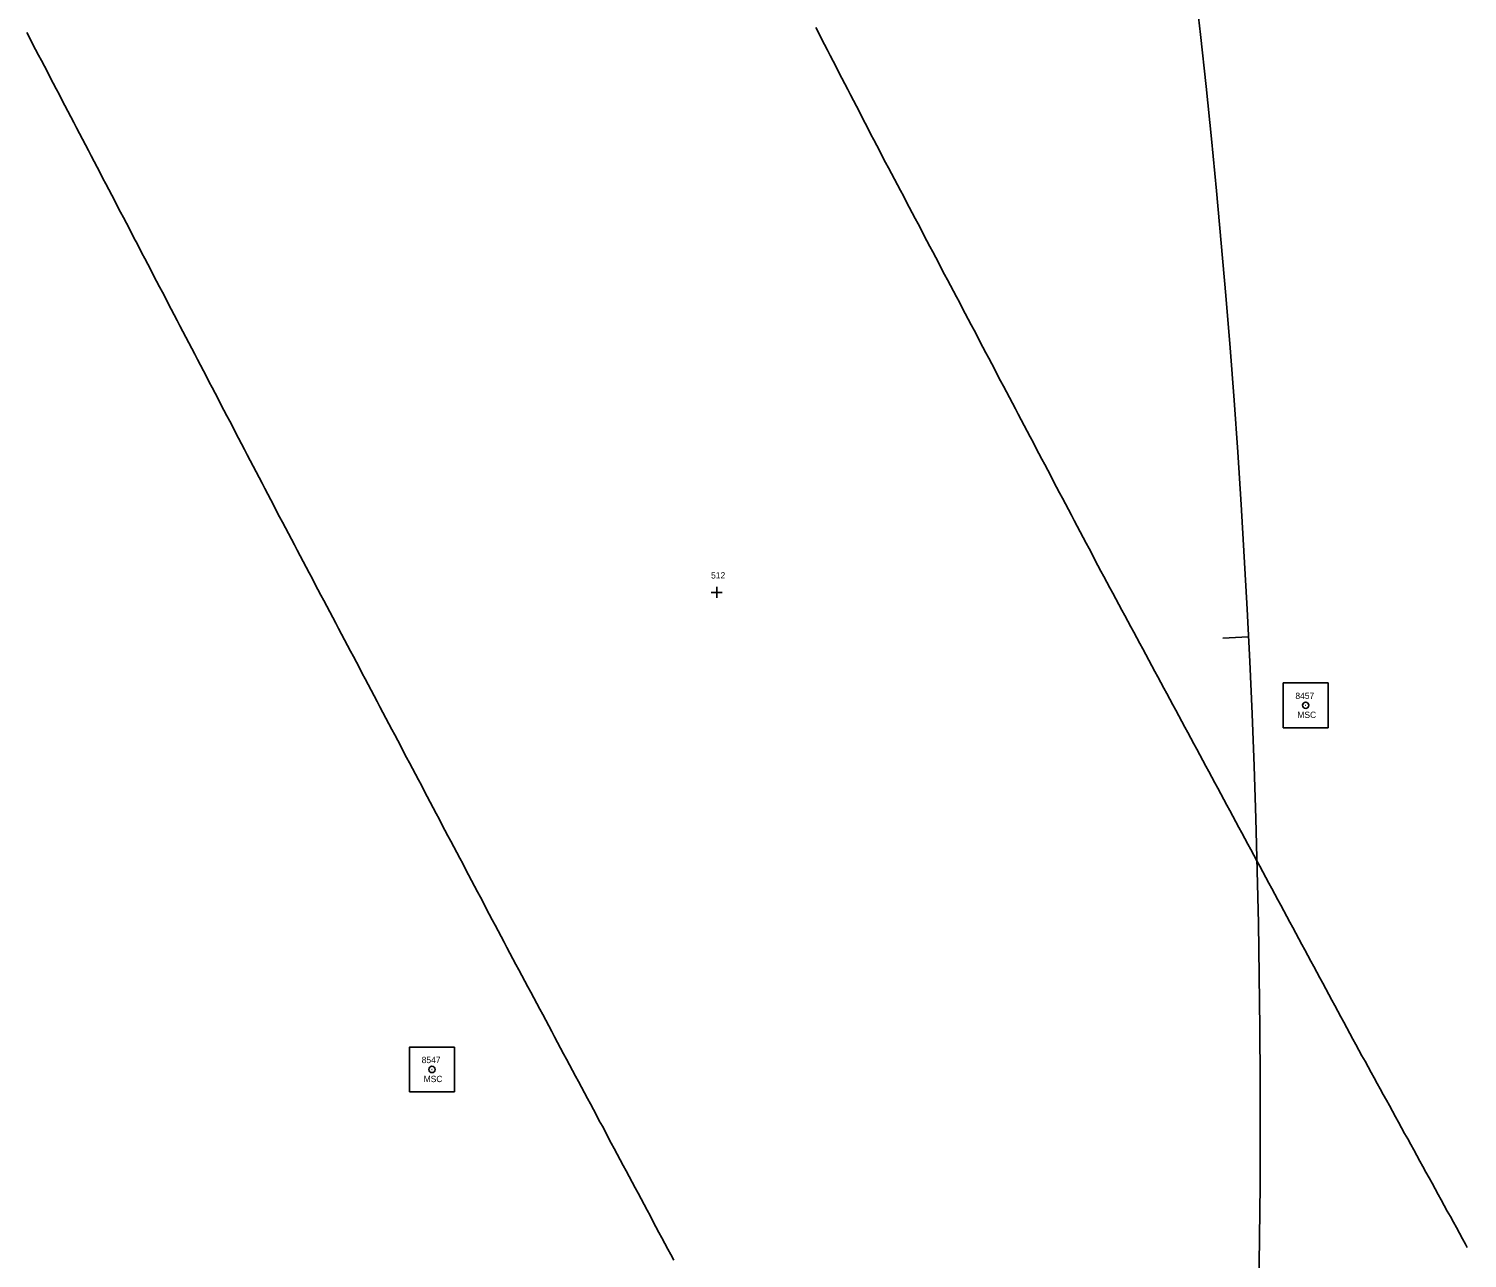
# Model space of a CAD drawing. Extents: x 205929 to 2357175, y -1785700 to 846739.
# Drawn here: x 2013567.6 to 2013794.9, y 822485.6 to 822679.9 of the extents above; entities that cross this region are included whole.
import ezdxf

# ---------------------------------------------------------------- set-up
doc = ezdxf.new("R2010")
doc.units = 0
for name, color, linetype in [('Default', 7, 'Continuous'), ('RD_HC_Cl', 7, 'Continuous'), ('RD_HC_Survey', 7, 'Continuous'), ('RD_HC_txCode', 7, 'Continuous'), ('RD_Sketch1', 7, 'Continuous'), ('RD_SMD_Locator', 7, 'Continuous')]:
    doc.layers.add(name, color=color, linetype=linetype)

msp = doc.modelspace()

# ---------------------------------------------------------------- linework, layer by layer
at = {"layer": 'Default'}
for p, q in [((2013677.23, 822590.79), (2013675.48, 822590.79)), ((2013676.35, 822591.66), (2013676.35, 822589.91))]:
    msp.add_line(p, q, dxfattribs=at)
at = {"layer": 'RD_HC_Cl'}
msp.add_line((2013760.34, 822583.77), (2013756.34, 822583.57), dxfattribs=at)
msp.add_arc((2012212.23, 822507.3), 1550, 316.11868, 35.79564, dxfattribs=at)
at = {"layer": 'RD_HC_Survey'}
for points in [[(2013772.95, 822576.48), (2013765.88, 822576.48), (2013765.88, 822569.41), (2013772.95, 822569.41)], [(2013634.89, 822518.95), (2013627.82, 822518.95), (2013627.82, 822511.88), (2013634.89, 822511.88)]]:
    msp.add_lwpolyline(points, close=True, dxfattribs=at)
for centre in [(2013769.42, 822572.95), (2013631.36, 822515.41)]:
    msp.add_circle(centre, 0.5, dxfattribs=at)
at = {"layer": 'RD_Sketch1'}
for points in [[(2013692, 822680.05), (2013692.46, 822679.17), (2013692.92, 822678.28), (2013693.38, 822677.39), (2013693.84, 822676.5), (2013694.3, 822675.61), (2013694.76, 822674.72), (2013695.22, 822673.83), (2013695.67, 822672.95), (2013696.13, 822672.06), (2013696.59, 822671.17), (2013697.05, 822670.28), (2013697.51, 822669.39), (2013697.97, 822668.5), (2013698.43, 822667.61), (2013698.89, 822666.73), (2013699.34, 822665.84), (2013699.8, 822664.95), (2013700.26, 822664.06), (2013700.72, 822663.17), (2013701.18, 822662.28), (2013701.64, 822661.4), (2013702.11, 822660.51), (2013702.57, 822659.63), (2013703.04, 822658.74), (2013703.51, 822657.86), (2013703.97, 822656.97), (2013704.44, 822656.09), (2013704.9, 822655.2), (2013705.37, 822654.32), (2013705.84, 822653.44), (2013706.3, 822652.55), (2013706.77, 822651.67), (2013707.23, 822650.78), (2013707.7, 822649.9), (2013708.16, 822649.01), (2013708.63, 822648.13), (2013709.1, 822647.24), (2013709.56, 822646.36), (2013710.03, 822645.47), (2013710.49, 822644.59), (2013710.96, 822643.71), (2013711.43, 822642.82), (2013711.89, 822641.94), (2013712.36, 822641.05), (2013712.82, 822640.17), (2013713.29, 822639.28), (2013713.75, 822638.4), (2013714.22, 822637.51), (2013714.69, 822636.63), (2013715.15, 822635.74), (2013715.62, 822634.86), (2013716.08, 822633.98), (2013716.55, 822633.09), (2013717.02, 822632.21), (2013717.48, 822631.32), (2013717.95, 822630.44), (2013718.41, 822629.55), (2013718.88, 822628.67), (2013719.35, 822627.78), (2013719.81, 822626.9), (2013720.28, 822626.01), (2013720.74, 822625.13), (2013721.21, 822624.24), (2013721.67, 822623.36), (2013722.14, 822622.48), (2013722.61, 822621.59), (2013723.07, 822620.71), (2013723.54, 822619.82), (2013724, 822618.94), (2013724.47, 822618.05), (2013724.94, 822617.17), (2013725.4, 822616.28), (2013725.87, 822615.4), (2013726.33, 822614.51), (2013726.8, 822613.63), (2013727.26, 822612.75), (2013727.73, 822611.86), (2013728.2, 822610.98), (2013728.66, 822610.09), (2013729.13, 822609.21), (2013729.59, 822608.32), (2013730.06, 822607.44), (2013730.53, 822606.55), (2013730.99, 822605.67), (2013731.46, 822604.78), (2013731.92, 822603.9), (2013732.39, 822603.02), (2013732.85, 822602.13), (2013733.32, 822601.25), (2013733.79, 822600.36), (2013734.25, 822599.48), (2013734.72, 822598.59), (2013735.18, 822597.71), (2013735.65, 822596.82), (2013736.12, 822595.94), (2013736.58, 822595.05), (2013737.05, 822594.17), (2013737.53, 822593.29), (2013738, 822592.41), (2013738.47, 822591.53), (2013738.95, 822590.65), (2013739.42, 822589.77), (2013739.9, 822588.89), (2013740.37, 822588.01), (2013740.84, 822587.13), (2013741.32, 822586.25), (2013741.79, 822585.37), (2013742.27, 822584.49), (2013742.74, 822583.61), (2013743.21, 822582.73), (2013743.69, 822581.85), (2013744.16, 822580.97), (2013744.64, 822580.08), (2013745.11, 822579.2), (2013745.59, 822578.32), (2013746.06, 822577.44), (2013746.53, 822576.56), (2013747.01, 822575.68), (2013747.48, 822574.8), (2013747.96, 822573.92), (2013748.43, 822573.04), (2013748.9, 822572.16), (2013749.38, 822571.28), (2013749.85, 822570.4), (2013750.33, 822569.52), (2013750.8, 822568.64), (2013751.27, 822567.76), (2013751.75, 822566.88), (2013752.22, 822566), (2013752.7, 822565.12), (2013753.17, 822564.24), (2013753.64, 822563.36), (2013754.12, 822562.48), (2013754.59, 822561.6), (2013755.07, 822560.72), (2013755.54, 822559.84), (2013756.01, 822558.95), (2013756.49, 822558.07), (2013756.96, 822557.19), (2013757.44, 822556.31), (2013757.91, 822555.43), (2013758.38, 822554.55), (2013758.86, 822553.67), (2013759.33, 822552.79), (2013759.81, 822551.91), (2013760.28, 822551.03), (2013760.75, 822550.15), (2013761.23, 822549.27), (2013761.7, 822548.39), (2013762.18, 822547.51), (2013762.65, 822546.63), (2013763.12, 822545.75), (2013763.6, 822544.87), (2013764.07, 822543.99), (2013764.55, 822543.11), (2013765.02, 822542.23), (2013765.5, 822541.35), (2013765.97, 822540.47), (2013766.44, 822539.59), (2013766.92, 822538.71), (2013767.39, 822537.82), (2013767.87, 822536.94), (2013768.34, 822536.06), (2013768.81, 822535.18), (2013769.29, 822534.3), (2013769.76, 822533.42), (2013770.24, 822532.54), (2013770.71, 822531.66), (2013771.18, 822530.78), (2013771.66, 822529.9), (2013772.13, 822529.02), (2013772.61, 822528.14), (2013773.08, 822527.26), (2013773.55, 822526.38), (2013774.03, 822525.5), (2013774.5, 822524.62), (2013774.98, 822523.74), (2013775.45, 822522.86), (2013775.92, 822521.98), (2013776.4, 822521.1), (2013776.87, 822520.22), (2013777.35, 822519.34), (2013777.83, 822518.46), (2013778.31, 822517.58), (2013778.79, 822516.71), (2013779.27, 822515.83), (2013779.76, 822514.95), (2013780.24, 822514.08), (2013780.72, 822513.2), (2013781.2, 822512.33), (2013781.68, 822511.45), (2013782.16, 822510.57), (2013782.64, 822509.7), (2013783.12, 822508.82), (2013783.61, 822507.94), (2013784.09, 822507.07), (2013784.57, 822506.19), (2013785.05, 822505.31), (2013785.53, 822504.44), (2013786.01, 822503.56), (2013786.49, 822502.69), (2013786.98, 822501.81), (2013787.46, 822500.93), (2013787.94, 822500.06), (2013788.42, 822499.18), (2013788.9, 822498.3), (2013789.38, 822497.43), (2013789.86, 822496.55), (2013790.34, 822495.67), (2013790.83, 822494.8), (2013791.31, 822493.92), (2013791.79, 822493.04), (2013792.27, 822492.17), (2013792.75, 822491.29), (2013793.23, 822490.42), (2013793.71, 822489.54), (2013794.2, 822488.66), (2013794.68, 822487.79), (2013794.94, 822487.3)], [(2013567.33, 822679.26), (2013567.8, 822678.37), (2013568.26, 822677.48), (2013568.72, 822676.6), (2013569.19, 822675.71), (2013569.65, 822674.82), (2013570.11, 822673.94), (2013570.58, 822673.05), (2013571.04, 822672.16), (2013571.5, 822671.28), (2013571.96, 822670.39), (2013572.43, 822669.51), (2013572.89, 822668.62), (2013573.35, 822667.73), (2013573.82, 822666.85), (2013574.28, 822665.96), (2013574.74, 822665.07), (2013575.21, 822664.19), (2013575.67, 822663.3), (2013576.13, 822662.42), (2013576.59, 822661.53), (2013577.06, 822660.64), (2013577.52, 822659.76), (2013577.98, 822658.87), (2013578.45, 822657.98), (2013578.91, 822657.1), (2013579.37, 822656.21), (2013579.84, 822655.33), (2013580.3, 822654.44), (2013580.76, 822653.55), (2013581.22, 822652.67), (2013581.69, 822651.78), (2013582.15, 822650.89), (2013582.61, 822650.01), (2013583.08, 822649.12), (2013583.54, 822648.24), (2013584, 822647.35), (2013584.47, 822646.46), (2013584.61, 822646.19), (2013585.07, 822645.31), (2013585.53, 822644.42), (2013585.99, 822643.54), (2013586.46, 822642.65), (2013586.92, 822641.76), (2013587.38, 822640.88), (2013587.84, 822639.99), (2013588.31, 822639.1), (2013588.77, 822638.22), (2013589.23, 822637.33), (2013589.69, 822636.44), (2013590.16, 822635.56), (2013590.62, 822634.67), (2013591.08, 822633.78), (2013591.54, 822632.9), (2013592.01, 822632.01), (2013592.47, 822631.12), (2013592.93, 822630.24), (2013593.4, 822629.35), (2013593.86, 822628.46), (2013594.32, 822627.58), (2013594.78, 822626.69), (2013595.25, 822625.8), (2013595.71, 822624.92), (2013596.17, 822624.03), (2013596.63, 822623.15), (2013597.1, 822622.26), (2013597.56, 822621.37), (2013598.02, 822620.49), (2013598.48, 822619.6), (2013598.95, 822618.71), (2013599.41, 822617.83), (2013599.87, 822616.94), (2013600.33, 822616.05), (2013600.8, 822615.17), (2013601.26, 822614.28), (2013601.72, 822613.39), (2013602.18, 822612.51), (2013602.65, 822611.62), (2013603.11, 822610.73), (2013603.57, 822609.85), (2013604.03, 822608.96), (2013604.5, 822608.07), (2013604.96, 822607.19), (2013605.42, 822606.3), (2013605.88, 822605.41), (2013606.35, 822604.53), (2013606.81, 822603.64), (2013607.27, 822602.76), (2013607.74, 822601.87), (2013608.21, 822600.99), (2013608.67, 822600.1), (2013609.14, 822599.22), (2013609.61, 822598.33), (2013610.07, 822597.45), (2013610.54, 822596.57), (2013611.01, 822595.68), (2013611.47, 822594.8), (2013611.94, 822593.91), (2013612.41, 822593.03), (2013612.87, 822592.14), (2013613.34, 822591.26), (2013613.81, 822590.37), (2013614.27, 822589.49), (2013614.74, 822588.61), (2013615.21, 822587.72), (2013615.67, 822586.84), (2013616.14, 822585.95), (2013616.61, 822585.07), (2013617.07, 822584.18), (2013617.54, 822583.3), (2013618.01, 822582.42), (2013618.47, 822581.53), (2013618.94, 822580.65), (2013619.41, 822579.76), (2013619.88, 822578.88), (2013620.34, 822577.99), (2013620.81, 822577.11), (2013621.28, 822576.22), (2013621.74, 822575.34), (2013622.21, 822574.46), (2013622.68, 822573.57), (2013623.14, 822572.69), (2013623.61, 822571.8), (2013624.08, 822570.92), (2013624.54, 822570.03), (2013625.01, 822569.15), (2013625.48, 822568.27), (2013625.94, 822567.38), (2013626.41, 822566.5), (2013626.88, 822565.61), (2013627.34, 822564.73), (2013627.81, 822563.84), (2013628.28, 822562.96), (2013628.74, 822562.07), (2013629.21, 822561.19), (2013629.68, 822560.31), (2013630.14, 822559.42), (2013630.61, 822558.54), (2013631.08, 822557.65), (2013631.54, 822556.77), (2013632.01, 822555.88), (2013632.48, 822555), (2013632.94, 822554.12), (2013633.41, 822553.23), (2013633.88, 822552.35), (2013634.34, 822551.46), (2013634.81, 822550.58), (2013635.28, 822549.69), (2013635.74, 822548.81), (2013636.21, 822547.93), (2013636.68, 822547.04), (2013637.14, 822546.16), (2013637.61, 822545.27), (2013638.08, 822544.39), (2013638.54, 822543.5), (2013639.01, 822542.62), (2013639.48, 822541.73), (2013639.94, 822540.85), (2013640.41, 822539.97), (2013640.88, 822539.08), (2013641.34, 822538.2), (2013641.81, 822537.31), (2013642.28, 822536.43), (2013642.74, 822535.54), (2013643.21, 822534.66), (2013643.68, 822533.78), (2013644.15, 822532.89), (2013644.62, 822532.01), (2013645.09, 822531.13), (2013645.56, 822530.25), (2013646.03, 822529.36), (2013646.5, 822528.48), (2013646.97, 822527.6), (2013647.44, 822526.72), (2013647.91, 822525.84), (2013648.39, 822524.95), (2013648.86, 822524.07), (2013649.33, 822523.19), (2013649.8, 822522.31), (2013650.27, 822521.43), (2013650.74, 822520.54), (2013651.21, 822519.66), (2013651.68, 822518.78), (2013652.15, 822517.9), (2013652.62, 822517.02), (2013653.1, 822516.13), (2013653.57, 822515.25), (2013654.04, 822514.37), (2013654.51, 822513.49), (2013654.98, 822512.61), (2013655.45, 822511.72), (2013655.92, 822510.84), (2013656.39, 822509.96), (2013656.86, 822509.08), (2013657.33, 822508.2), (2013657.8, 822507.31), (2013658.28, 822506.43), (2013658.75, 822505.55), (2013659.22, 822504.67), (2013659.69, 822503.79), (2013660.16, 822502.9), (2013660.63, 822502.02), (2013661.1, 822501.14), (2013661.57, 822500.26), (2013662.04, 822499.38), (2013662.51, 822498.49), (2013662.99, 822497.61), (2013663.46, 822496.73), (2013663.93, 822495.85), (2013664.4, 822494.97), (2013664.87, 822494.08), (2013665.34, 822493.2), (2013665.81, 822492.32), (2013666.28, 822491.44), (2013666.75, 822490.56), (2013667.22, 822489.67), (2013667.7, 822488.79), (2013668.17, 822487.91), (2013668.64, 822487.03), (2013669.11, 822486.15), (2013669.58, 822485.26)]]:
    msp.add_lwpolyline(points, dxfattribs=at)
at = {"layer": 'RD_SMD_Locator'}
for centre in [(2013769.42, 822572.95), (2013631.36, 822515.41)]:
    msp.add_circle(centre, 0.001, dxfattribs=at)

# ---------------------------------------------------------------- texts
at = {"layer": 'Default'}
msp.add_text('512', height=1, dxfattribs=at).set_placement((2013675.46, 822592.99))
at = {"layer": 'RD_HC_txCode'}
for s, p in [('8457', (2013767.79, 822573.95)), ('MSC', (2013768.1, 822570.95)), ('8547', (2013629.73, 822516.41)), ('MSC', (2013630.04, 822513.41))]:
    msp.add_text(s, height=1, dxfattribs=at).set_placement(p)

doc.saveas('drawing.dxf')
